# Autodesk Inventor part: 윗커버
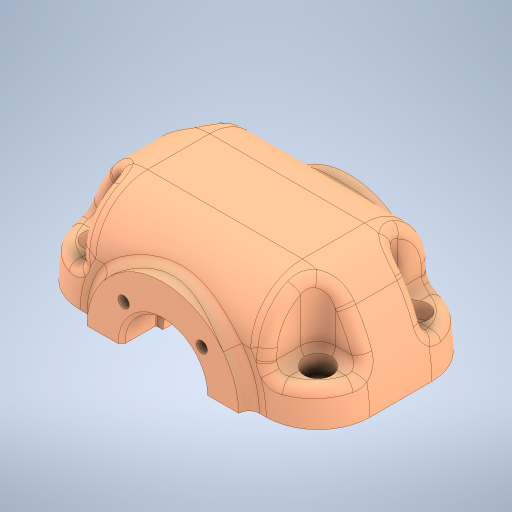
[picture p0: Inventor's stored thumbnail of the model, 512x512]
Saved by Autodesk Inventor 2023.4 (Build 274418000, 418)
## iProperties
Created: 2024-05
Part Number: 윗커버
Material: 알루미늄 6061
Document SubType Name: Modeling
Designer: EDU-001
Density: 2.7 g/cm^3
Appearance: 기본값
Author: jhkim
Sending System: Autodesk Inventor 2025
Preprocessor: ST-DEVELOPER v20
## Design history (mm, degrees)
node "윗커버1"
node "솔리드2"
node "솔리드1"
